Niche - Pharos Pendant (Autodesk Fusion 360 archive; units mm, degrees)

design "Pharos" references "Pharos", "Niche - Chief Architect - Luxe Single Pendant Cordset", "Luxe Single Pendant Cordset - 4ft Standard"
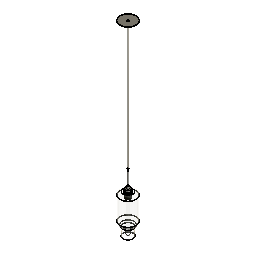
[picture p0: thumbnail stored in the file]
external_derived "ExternalDerived1"
external_derived "ExternalDerived2" bodies "Socket Body", "Shade Ring", "Shade Ring +Collar", "Socket", "Body1 (1)", "Metal Strain Relief", "Fabric Cord (1)", "Stem (Threaded)"
move "Move1"
external_derived "ExternalDerived3" bodies "T8-Bulb"
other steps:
derived_base_feature "Derived Base Feature1" bodies "Body1"
derived_base_feature "Derived Base Feature2" bodies "Socket Body", "Shade Ring", "Shade Ring +Collar", "Socket", "Body1 (1)", "Metal Strain Relief", "Fabric Cord (1)", "Stem (Threaded)"
derived_base_feature "Derived Base Feature3" bodies "T8-Bulb"
named bodies: "Body1", "Socket Body", "Shade Ring", "Shade Ring +Collar", "Socket", "Body1 (1)", "Metal Strain Relief", "Fabric Cord (1)", "Stem (Threaded)", "Cap (Threaded)", "T8-Bulb"

design "Luxe Single Pendant Cordset - 4ft Standard" references "Luxe Canopy - Single Pendant Cordset"
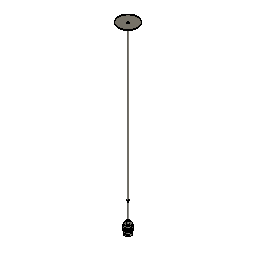
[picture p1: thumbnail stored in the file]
external_derived "ExternalDerived2" bodies "Cap (Threaded)"
move "Move1"
move "Move2"
offset_faces "OffsetFaces1" distance 1051.56
move "Move3"
move "Move4"
move "Move5"
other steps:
derived_base_feature "Derived Base Feature9" bodies "Socket Body", "Shade Ring", "Shade Ring +Collar", "Socket"
derived_base_feature "Derived Base Feature10" bodies "Body1"
derived_base_feature "Derived Base Feature12" bodies "Metal Strain Relief"
derived_base_feature "Derived Base Feature13" bodies "Fabric Cord (1)"
derived_base_feature "Derived Base Feature14" bodies "Stem (Threaded)"
derived_base_feature "Derived Base Feature15" bodies "Cap 9Threaded)", "Cap (Threaded)"
named bodies: "Socket Body", "Shade Ring", "Shade Ring +Collar", "Socket", "Metal Strain Relief", "Fabric Cord (1)", "Stem (Threaded)", "Cap 9Threaded)", "Body1", "Cap (Threaded)", "5M Set Screw"

design "Pharos"
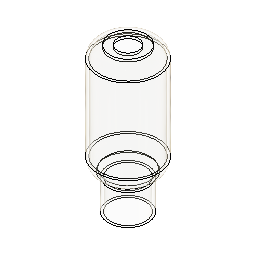
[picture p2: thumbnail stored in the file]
sketch "Sketch1" plane through (0, 0, 0) normal (0, 1, 0) x axis (1, 0, 0)
  line L1 (63.5, 0) -> (25.4, 0)
  line L2 (0, -234.95) -> (0, -25.4)
  line L3 (63.5, -368.3) -> (63.5, 0)
  line L4 (95.1552, -330.2058) -> (22.1208, -330.198)
  line L5 (88.9054, -330.2051) -> (95.1552, -330.2058)
  line L6 (127, -381) -> (0, -381)
  line L7 (63.5, -438.8463) -> (63.5, -381)
  line L8 (104.775, -409.9232) -> (63.5, -409.9232)
  line L9 (22.225, -409.9232) -> (63.5, -409.9232)
  line L10 (22.225, -342.9604) -> (22.225, -409.9232)
  line L11 (98.425, -234.95) -> (98.425, 0)
  line L12 (22.1304, -240.8815) -> (22.1208, -330.198)
  arc A1 centre (25.4, -25.4) radius 25.4 clockwise from (0, -25.4) to (25.4, 0)
  arc A2 centre (30.6129, -203.4011) radius 30.6143 clockwise from (15.9842, -230.2942) to (0, -203.1036)
  arc A3 centre (9.9384, -240.8815) radius 12.192 clockwise from (15.9842, -230.2942) to (22.1304, -240.8841)
  point P9 (88.9054, -330.2051)
  point P12 (63.5, -381)
  point P14 (63.5, -409.9232)
  point P21 (0, -203.1036)
  point P26 (22.1304, -240.8841)
  point P24 (22.1304, -240.8815)
  point P1 (0, 0)
  point P6 (0, -234.95)
  point P10 (0, -381)
  point P11 (127, -381)
  point P15 (104.775, -409.9232)
  point P16 (22.225, -409.9232)
  point P18 (98.425, 0)
  point P19 (98.425, -234.95)
  perpendicular L1 L3
  coincident L4 P9
  midpoint L6 P12
  perpendicular L6 L7
  midpoint L7 P14
  perpendicular L7 L8
  perpendicular L7 L9
  perpendicular L9 L10
  vertical L11
  coincident L2 P21
  perpendicular L4 L12
  coincident L12 P26
  coincident P24 A3
  dimension "d1" diameter A1 = 50.8
  dimension "d4" distance P1 P6 = 234.95
  dimension "d12" distance P10 P11 = 127
  dimension "d13" distance P14 P15 = 41.275
  dimension "d14" distance P14 P16 = 41.275
  dimension "d15" distance P18 P19 = 234.95
  dimension "d20" diameter A3 = 24.384
revolve "Revolve1" sketch "Sketch1" AlongAngle 360
offset_faces "OffsetFaces1" distance -25.4
shell "Shell1" innerThickness 5
sketch "Sketch2" plane through (0, 0, 0) normal (0, 0, -1) x axis (1, 0, 0)
  circle C1 centre (63.5, 0) radius 38.1
  circle C2 centre (63.5, 0) radius 22.225
  concentric C1 C2
  dimension "d23" diameter C2 = 44.45 (= "1 3/4")
extrude "Extrude1" cut sketch "Sketch2" profile of C2 against normal blind 50.8
move "Move1"

design "Luxe Canopy - Single Pendant Cordset" references "M5 Set Screw", "Canopy Mounting Bar", "Plastic Strain Relief", "Canopy Mounting Bar Screw", "Luxe Cordset"
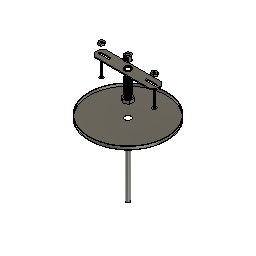
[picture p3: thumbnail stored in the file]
sketch "Sketch1" plane through (0, 0, 0) normal (0, 0, 1) x axis (1, 0, 0)
  circle C1 centre (0, 0) radius 63.5
  point P1 (0, 0)
  point P2 (0, 0)
  coincident P1 P2
  dimension "d1" diameter C1 = 127
extrude "Extrude1" new body sketch "Sketch1" along normal blind 5.08
shell "Shell1" innerThickness 0.762
hole "Hole1" HoleDepth 35.56 HoleDiameter 10.16 TipAngle 118
component_from_bodies "Body->Comp1"
component_insert "Component Insert1"
component_insert "Component Insert2"
component_insert "Component Insert3"
sketch "Sketch2" plane through (0, 0, 0) normal (0, 0, 1) x axis (1, 0, 0)
  circle C1 centre (0, 0) radius 3.175
  point P1 (0, 0)
  point P2 (0, 0)
  coincident P1 P2
  dimension "d8" diameter C1 = 6.35
extrude "Extrude2" new body sketch "Sketch2" along normal blind 127 and against normal blind 127 bodies "Fabric Cord"
component_insert "Component Insert4"
component_insert "Component Insert5"
position "Position1"
sketch "Sketch3" plane through (0, 0, 0.762) normal (0, 0, 1) x axis (-1, 0, 0)
  circle C1 centre (-0.0475, 0.2257) radius 5.08
  circle C2 centre (0, 0) radius 62.738
  circle C3 centre (0, 0) radius 4.826
  concentric C2 C3
  dimension "d13" diameter C3 = 9.652
extrude "Extrude3" new body sketch "Sketch3" profile of C3 along normal blind 25.4 bodies "Threaded Nipple"
shell "Shell2" innerThickness 1.27
thread "Thread1"
sketch "Sketch5" plane through (0, 0, 127) normal (0, 0, 1) x axis (-1, 0, 0)
  line L1 (-6.8191, 3.937) -> (0, 7.874)
  line L2 (-6.8191, -3.937) -> (-6.8191, 3.937)
  line L3 (0, -7.874) -> (-6.8191, -3.937)
  line L4 (6.8191, -3.937) -> (0, -7.874)
  line L5 (6.8191, 3.937) -> (6.8191, -3.937)
  line L6 (0, 7.874) -> (6.8191, 3.937)
  circle C1 centre (0, 0) radius 3.175
  point P2 (0, 0)
  point P9 (0, 0)
  point P3 (0, 7.874)
  coincident P2 P9
  dimension "d20" distance P3 P9 = 7.874
extrude "Extrude4" new body sketch "Sketch5" along normal blind 5.08 bodies "Hex Nut"
move "Move1"
thread "Thread2"
move "Move2" TranslateX 0 TranslateY 0 TranslateZ -55.88
move "Move3" TranslateX 0 TranslateY 0 TranslateZ 60.96
position "Position2"
sketch "Sketch6" plane through (0, 0, 0) normal (0, 0, 1) x axis (1, 0, 0)
  circle C1 centre (0, 0) radius 9.525
  point P1 (0, 0)
  point P2 (0, 0)
  coincident P1 P2
  dimension "d29" diameter C1 = 19.05
extrude "Extrude5" new body sketch "Sketch6" along normal blind 16.129 bodies "Metal Strain Relief"
move "Move4" TranslateX 0 TranslateY 0 TranslateZ -86.36
hole "Hole2" HoleDepth 10.16 HoleDiameter 5.08 TipAngle 118
hole "Hole3" HoleDepth 4.064 HoleDiameter 7.62 TipAngle 180
hole "Hole4" HoleDepth 12.192 HoleDiameter 9.144 TipAngle 180
thread "Thread3" ThreadOffset 0 ThreadLength 6.096
move "Move1" TranslateX 0 TranslateY 0 TranslateZ 68.58
move "Move5" TranslateX 0 TranslateY 0 TranslateZ 138.43
component_insert "Component Insert6"
external_derived "ExternalDerived1" bodies "5M Set Screw"
move "Move6" TranslateX 0 TranslateY 0 TranslateZ -185.42
copy_paste_bodies "CopyPasteBodies1"
move "Move7" TranslateX 0 TranslateY 0 TranslateZ -12.7
offset_faces "OffsetFaces1" distance -152.4
move "Move8"
component_from_bodies "Body->Comp2"
component_from_bodies "Body->Comp3"
component_from_bodies "Body->Comp4"
component_from_bodies "Body->Comp5"
hole "Hole1" HoleDepth 25.4 HoleDiameter 6.35 TipAngle 180
sketch "Sketch7" plane through (0, 0, 0) normal (0, 0, 1) x axis (1, 0, 0)
  line L1 (49.784, 3.9595) -> (52.07, 0)
  line L2 (45.212, 3.9595) -> (49.784, 3.9595)
  line L3 (42.926, 0) -> (45.212, 3.9595)
  line L4 (45.212, -3.9595) -> (42.926, 0)
  line L5 (49.784, -3.9595) -> (45.212, -3.9595)
  line L6 (52.07, 0) -> (49.784, -3.9595)
  point P2 (52.07, 0)
  point P8 (47.498, 0)
  dimension "d63" distance P2 P8 = 4.572
extrude "Extrude6" new body sketch "Sketch7" along normal blind 3.175 bodies "Mounting Hex Nut"
hole "Hole5" HoleDepth 25.4 HoleDiameter 3.81 TipAngle 180
thread "Thread4"
move "Move9"
component_from_bodies "Body->Comp6"
copy_paste "CopyPaste1"
move "Move10"
derived_base_feature "Derived Base Feature3" bodies "Stem (Threaded)", "Cap 9Threaded)"
move "Move11"
component_from_bodies "Body->Comp7"
component_from_bodies "Body->Comp8"
component_from_bodies "Body->Comp9"
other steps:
base_feature "Base Feature1"
base_feature "Base Feature1" bodies "Stem (Threaded)"
base_feature "Base Feature1" bodies "Cap 9Threaded)"
base_feature "Base Feature1" bodies "Fabric Cord"
base_feature "Base Feature1" bodies "Metal Strain Relief"
base_feature "Base Feature1" bodies "Mounting Hex Nut"
base_feature "Base Feature1" bodies "Hex Nut"
base_feature "Base Feature1" bodies "Fabric Cord (1)"
base_feature "Base Feature1" bodies "Threaded Nipple"
derived_base_feature "Derived Base Feature1" bodies "Socket Body", "Shade Ring", "Shade Ring +Collar", "Socket", "Rigid Stem"
derived_base_feature "Derived Base Feature2" bodies "5M Set Screw"
base_feature "Base Feature1" bodies "Fabric Cord", "Fabric Cord (1)"
create_component "CreateComponent1"
remove_body "RemoveBody1"
create_component "CreateComponent2"
remove_body "RemoveBody2"
create_component "CreateComponent3"
remove_body "RemoveBody3"
create_component "CreateComponent4"
remove_body "RemoveBody4"
create_component "CreateComponent5"
remove_body "RemoveBody5"
create_component "CreateComponent6"
remove_body "RemoveBody6"
create_component "CreateComponent7"
remove_body "RemoveBody7"
create_component "CreateComponent8"
remove_body "RemoveBody8"
create_component "CreateComponent9"
remove_body "RemoveBody9"
named bodies: "Fabric Cord", "Threaded Nipple", "Hex Nut", "Metal Strain Relief", "Socket Body", "Shade Ring", "Shade Ring +Collar", "Socket", "Rigid Stem", "5M Set Screw", "Fabric Cord (1)", "Mounting Hex Nut", "Stem (Threaded)", "Cap 9Threaded)"

design "M5 Set Screw"
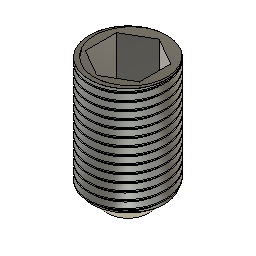
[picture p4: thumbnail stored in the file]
sketch "Sketch1" plane through (0, 0, 0) normal (0, 0, 1) x axis (1, 0, 0)
  circle C1 centre (0, 0) radius 2.5
  point P1 (0, 0)
  point P2 (0, 0)
  coincident P1 P2
  dimension "d1" diameter C1 = 5
extrude "Extrude1" new body sketch "Sketch1" along normal blind 8
sketch "Sketch2" plane through (0, 0, 8) normal (0, 0, 1) x axis (-1, 0, 0)
  line L1 (-1.7321, 1) -> (0, 2)
  line L2 (-1.7321, -1) -> (-1.7321, 1)
  line L3 (0, -2) -> (-1.7321, -1)
  line L4 (1.7321, -1) -> (0, -2)
  line L5 (1.7321, 1) -> (1.7321, -1)
  line L6 (0, 2) -> (1.7321, 1)
  circle C1 centre (0, 0) radius 2.5
  point P2 (0, 0)
  point P9 (0, 0)
  coincident P2 P9
extrude "Extrude2" cut sketch "Sketch2" profile of L1 L2 L3 L4 L5 L6 against normal blind 3
thread "Thread1" ThreadOffset 0.99 ThreadLength 7
chamfer "Chamfer1" distance 1.15

design "Luxe Cordset" references "M5 Set Screw"
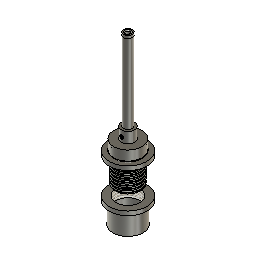
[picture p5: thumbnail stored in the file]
sketch "Sketch1" plane through (0, 0, 0) normal (0, 0, 1) x axis (1, 0, 0)
  circle C1 centre (0, 0) radius 20.6
  point P1 (0, 0)
  point P2 (0, 0)
  coincident P1 P2
  dimension "d11" diameter C1 = 41.2
extrude "Extrude1" new body sketch "Sketch1" along normal blind 14 bodies "Socket Body"
sketch "Sketch2" plane through (0, 0, 14) normal (0, 0, 1) x axis (-1, 0, 0)
  circle C1 centre (0, 0) radius 20.6
  circle C2 centre (0, 0) radius 9.6
  concentric C1 C2
  dimension "d3" diameter C2 = 19.2
extrude "Extrude2" add sketch "Sketch2" profile of C2 along normal blind 15.75
sketch "Sketch3" plane through (0, 0, 29.75) normal (0, 0, 1) x axis (-1, 0, 0)
  circle C1 centre (0, 0) radius 9.6
  circle C2 centre (0, 0) radius 5.75
  concentric C1 C2
  dimension "d6" diameter C2 = 11.5
extrude "Extrude3" new body sketch "Sketch3" profile of C2 along normal blind 114 bodies "Rigid Stem"
move "Move1"
sketch "Sketch4" plane through (0, 0, 203.75) normal (0, 0, 1) x axis (-1, 0, 0)
  circle C1 centre (0, 0) radius 5.75
  circle C2 centre (0, 0) radius 27.5
  dimension "d10" diameter C2 = 55
extrude "Extrude4" new body sketch "Sketch4" profile of C2 along normal blind 6 bodies "Shade Ring"
hole "Hole1" HoleDepth 25 HoleDiameter 42.75 TipAngle 118
sketch "Sketch5" plane through (0, 0, 0) normal (0, 0, 1) x axis (1, 0, 0)
  circle C1 centre (0, 0) radius 22
  point P1 (0, 0)
  point P2 (0, 0)
  coincident P1 P2
  dimension "d18" diameter C1 = 44
move "Move2"
copy_paste_bodies "CopyPasteBodies1"
move "Move3"
sketch "Sketch6" plane through (0, 0, 60) normal (0, 0, -1) x axis (1, 0, 0)
  circle C1 centre (0, 0) radius 20.6
  circle C2 centre (0, 0) radius 21.375
  circle C3 centre (0, 0) radius 20
  concentric C1 C2
  concentric C1 C3
  dimension "d21" diameter C2 = 42.75
  dimension "d24" diameter C3 = 40
cylinder_primitive "CylinderPrimitive1" Height 8 Diameter 42.75
thread "Thread1"
thread "Thread3"
hole "Hole2" HoleDepth 18 HoleDiameter 39 TipAngle 180
move "Move4"
move "Move5"
move "Move6"
hole "Hole3" HoleDepth 114 HoleDiameter 7.6 TipAngle 180
derived_base_feature "Derived Base Feature" bodies "Socket"
move "Move7"
scale "Scale1" ScaleX 1.2 ScaleY 1.2
move "Move8"
sketch "Sketch8" plane through (0, 0, -23.9827) normal (0, 0, -1) x axis (1, 0, 0)
  circle C1 centre (0, -0.036) radius 27.5
  circle C2 centre (0, -0.036) radius 22
  circle C3 centre (0, -0.036) radius 19.5
  dimension "d36" diameter C2 = 44
  dimension "d42" = -2.5
extrude "Extrude7" add sketch "Sketch8" profile of C2 C3 along normal blind 30
offset_faces "OffsetFaces1" distance 2.75
offset_faces "OffsetFaces2" distance -9
thread "Thread2"
move "Move9"
move "Move10"
move "Move11"
scale "Scale2" ScaleZ 1.2
move "Move12"
move "Move13"
move "Move14"
move "Move15"
move "Move16"
split_face "SplitFace1"
move "Move17"
move "Move18"
move "Move19"
move "Move20"
move "Move21"
move "Move22"
move "Move23"
move "Move24"
move "Move25"
move "Move26"
move "Move27"
thread "Thread4"
move "Move28"
move "Move29"
move "Move30"
hole "Hole4" HoleDepth 21 HoleDiameter 39.35 TipAngle 180
hole "Hole5" HoleDepth 9 HoleDiameter 5 TipAngle 180
move "Move31"
move "Move32"
hole "Hole6" HoleDepth 20 HoleDiameter 10 TipAngle 180
move_face "MoveFace3"
move "Move33"
move "Move34"
move "Move35"
move "Move36"
move "Move37"
thread "Thread5" ThreadOffset 0 ThreadLength 6
thread "Thread6" ThreadOffset 0 ThreadLength 6
move "Move38"
move "Move39"
move "Move40"
move "Move41"
component_insert "Component Insert"
thread "Thread7" ThreadOffset 0.5 ThreadLength 5.337
chamfer "Chamfer1" distance 0.5 distance 0.35
sketch "Sketch12" plane through (0, 0, 0) normal (0, 0, 1) x axis (1, 0, 0)
  circle C1 centre (0, 0) radius 6.35
  dimension "d60" diameter C1 = 12.7
extrude "Extrude8" new body sketch "Sketch12" along normal blind 115 bodies "Stem (Threaded)"
hole "Hole7" HoleDepth 115 HoleDiameter 9.65 TipAngle 118
thread "Thread8" ThreadOffset 0 ThreadLength 12.5
thread "Thread9" ThreadOffset 0 ThreadLength 12.5
sketch "Sketch13" plane through (0, 0, 0) normal (0, 0, 1) x axis (1, 0, 0)
  circle C1 centre (0, 0) radius 6.35
  point P1 (0, 0)
  point P2 (0, 0)
  coincident P1 P2
  dimension "d70" diameter C1 = 12.7
extrude "Extrude9" new body sketch "Sketch13" along normal blind 4 bodies "Cap 9Threaded)"
sketch "Sketch14" plane through (0, 0, 4) normal (0, 0, 1) x axis (-1, 0, 0)
  circle C1 centre (0, 0) radius 6.35
  circle C2 centre (0, 0) radius 4.5
  concentric C1 C2
  dimension "d73" diameter C2 = 9
extrude "Extrude10" add sketch "Sketch14" profile of C2 against normal blind 14
thread "Thread10"
hole "Hole8" HoleDepth 115 HoleDiameter 6.5 TipAngle 118 CSDiameter 9 CSAngle 90
move "Move42"
move "Move43"
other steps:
base_feature "Base Feature" bodies "Shade Ring +Collar"
named bodies: "Socket Body", "Shade Ring", "Shade Ring +Collar", "Socket", "Rigid Stem", "Stem (Threaded)", "Cap 9Threaded)"

design "Plastic Strain Relief"
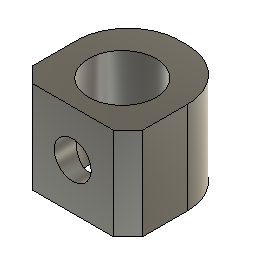
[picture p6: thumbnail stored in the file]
base_feature "Base Feature" bodies "strainrelief"
named bodies: "strainrelief"

design "Canopy Mounting Bar Screw"
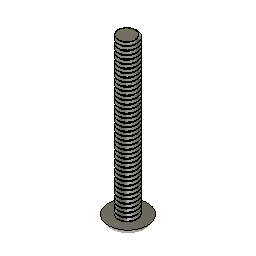
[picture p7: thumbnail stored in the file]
base_feature "Base Feature" bodies "screw1"
named bodies: "screw1"

design "Canopy Mounting Bar"
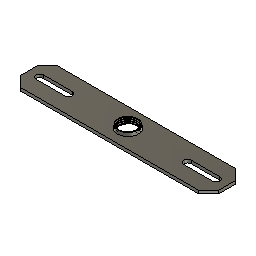
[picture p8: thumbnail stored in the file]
base_feature "Base Feature" bodies "mountingbar"
named bodies: "mountingbar"

design "Niche - Chief Architect - Luxe Single Pendant Cordset"
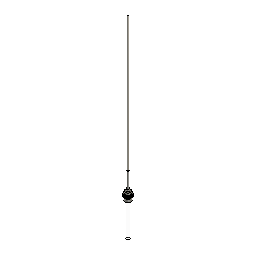
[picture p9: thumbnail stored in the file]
derived_base_feature "Derived Base Feature" bodies "Socket Body", "Shade Ring", "Shade Ring +Collar", "Socket", "Canopy", "Metal Strain Relief", "Fabric Cord (1)", "Stem (Threaded)"
remove_body "RemoveBody1"
remove_body "RemoveBody2"
split "Split1" bodies "Socket Body (1)"
remove_body "RemoveBody3"
align "Align1"
hole "Hole1" HoleDepth 19.05 HoleDiameter 8.89 TipAngle 118
combine "Combine1" bodies "Shade Ring"
split "Split2" bodies "Socket (1)"
remove_body "RemoveBody4"
split "Split3" bodies "Fabric Cord (1) (1)"
remove_body "RemoveBody5"
combine "Combine2" bodies "Socket Body"
align "Align2"
combine "Combine3" bodies "Metal Strain Relief"
sketch "Sketch1" plane through (0, 0, 0) normal (0, 1, 0) x axis (1, 0, 0)
  line L1 (13.1098, 24.9049) -> (-12.2902, 24.9049)
  line L2 (18.1898, 37.1766) -> (18.1898, 29.9849)
  line L3 (-17.3702, 29.9849) -> (-17.3702, 36.7132)
  line L4 (0, 132.969) -> (0, 24.9049)
  arc A1 centre (0, 86.36) radius 46.609 clockwise from (-22.6031, 45.5985) to (23.276, 45.979)
  arc A2 centre (-27.5302, 36.7132) radius 10.16 clockwise from (-22.6031, 45.5985) to (-17.3702, 36.7132)
  arc A3 centre (28.3498, 37.1766) radius 10.16 clockwise from (18.1898, 37.1766) to (23.276, 45.979)
  arc A4 centre (-12.2902, 29.9849) radius 5.08 clockwise from (-12.2902, 24.9049) to (-17.3702, 29.9849)
  arc A5 centre (13.1098, 29.9849) radius 5.08 clockwise from (18.1898, 29.9849) to (13.1098, 24.9049)
  point P5 (18.1898, 43.4469)
  point P3 (-17.3702, 24.9049)
  point P4 (18.1898, 24.9049)
  point P18 (0, 24.9049)
  point P19 (0, 132.969)
  horizontal L1
  vertical L2
  vertical L3
  tangent A1 A2
  tangent L3 A2
  coincident P5 L2
  coincident P5 A1
  tangent L2 A3
  tangent A1 A3
  equal A2 A3
  coincident P3 L1
  coincident P3 L3
  tangent L1 A4
  tangent L3 A4
  coincident P4 L1
  coincident P4 L2
  tangent L1 A5
  tangent L2 A5
  coincident L1 P18
  coincident A1 P19
  perpendicular L1 L4
  dimension "d4" diameter A1 = 93.218
  dimension "d5" distance P3 P4 = 35.56
  dimension "d6" distance P4 P5 = 18.542
  dimension "d7" radius A2 = 10.16
  dimension "d8" radius A4 = 5.08
  dimension "d9" radius A5 = 5.08
revolve "Revolve1" sketch "Sketch1" AlongAngle 360 bodies "G30-Bulb"
move "Move1"
sketch "Sketch2" plane through (0, 0, 0) normal (0, 1, 0) x axis (1, 0, 0)
  line L1 (12.7, 0) -> (-12.7, 0)
  line L2 (12.7, 152.4) -> (12.7, 0)
  line L3 (-12.7, 0) -> (-12.7, 152.4)
  line L4 (0, 165.1) -> (0, 0)
  arc A1 centre (0, 152.4) radius 12.7 clockwise from (-12.7, 152.4) to (12.7, 152.4)
  point P1 (0, 0)
  point P7 (0, 0)
  point P8 (0, 165.1)
  horizontal L1
  vertical L2
  vertical L3
  coincident P1 P7
  midpoint A1 P8
  perpendicular L1 L4
revolve "Revolve2" sketch "Sketch2" AlongAngle 360 bodies "T9-Bulb"
move "Move2"
sketch "Sketch3" plane through (0, 0, 0) normal (0, 1, 0) x axis (1, 0, 0)
  line L1 (12.7, 0) -> (-12.7, 0)
  line L2 (12.7, 254) -> (12.7, 0)
  line L3 (-12.7, 0) -> (-12.7, 254)
  line L4 (0, 266.7) -> (0, 0)
  arc A1 centre (0, 254) radius 12.7 clockwise from (-12.7, 254) to (12.7, 254)
  point P1 (0, 0)
  point P7 (0, 0)
  point P8 (0, 266.7)
  horizontal L1
  vertical L2
  vertical L3
  coincident P1 P7
  midpoint A1 P8
  perpendicular L1 L4
revolve "Revolve3" sketch "Sketch3" AlongAngle 360 bodies "T8-Bulb"
move "Move3"
move "Move4"
move "Move5"
sketch "Sketch4" plane through (0, 0, 0) normal (0, 1, 0) x axis (1, 0, 0)
  line L1 (15.875, -8.763) -> (-15.875, -8.763)
  line L2 (15.875, 22.987) -> (15.875, -8.763)
  line L3 (-15.875, 22.987) -> (15.875, 22.987)
  line L4 (-15.875, -8.763) -> (-15.875, 22.987)
  line L5 (0, 22.987) -> (0, -8.763)
  point P6 (0, -8.763)
  point P7 (0, 22.987)
  point P2 (-15.875, -8.763)
  point P3 (15.875, -8.763)
  point P5 (-15.875, 22.987)
  horizontal L1
  vertical L2
  horizontal L3
  vertical L4
  midpoint L1 P6
  midpoint L3 P7
  dimension "d13" distance P2 P3 = 31.75
  dimension "d14" distance P2 P5 = 31.75
revolve "Revolve4" sketch "Sketch4" AlongAngle 360 bodies "Bulb Extender"
move "Move6"
sketch "Sketch5" plane through (0, 0, 0) normal (0, 1, 0) x axis (1, 0, 0)
  line L1 (-12.7, 35.56) -> (12.7, 35.56)
  line L2 (-12.7, 5.08) -> (-12.7, 35.56)
  line L3 (12.7, 5.08) -> (-12.7, 5.08)
  line L4 (12.7, 35.56) -> (12.7, 5.08)
  line L5 (-12.7, 5.08) -> (12.7, 35.56)
  line L6 (12.7, 5.08) -> (-12.7, 35.56)
  line L7 (0, 35.56) -> (0, 5.08)
  point P6 (0, 20.32)
  point P7 (0, 5.08)
  point P8 (0, 35.56)
  horizontal L1
  perpendicular L1 L2
  parallel L1 L3
  parallel L2 L4
  coincident L5 P6
  coincident L6 P6
  midpoint L3 P7
  midpoint L1 P8
revolve "Revolve5" sketch "Sketch5" AlongAngle 360 bodies "Y-Spliter"
sketch "Sketch6" plane through (0, 0, 0) normal (0, 1, 0) x axis (1, 0, 0)
  line L1 (-55.88, 64.9514) -> (-21.59, 64.9514)
  line L2 (-55.88, 35.7414) -> (-55.88, 64.9514)
  line L3 (-21.59, 35.7414) -> (-55.88, 35.7414)
  line L4 (-21.59, 64.9514) -> (-21.59, 35.7414)
  line L5 (-55.88, 35.7414) -> (-21.59, 64.9514)
  line L6 (-21.59, 35.7414) -> (-55.88, 64.9514)
  line L7 (-38.735, 64.9514) -> (-38.735, 35.7414)
  point P6 (-38.735, 50.3464)
  point P7 (-38.735, 35.7414)
  point P8 (-38.735, 64.9514)
  point P4 (-55.88, 35.7414)
  point P5 (-21.59, 35.7414)
  point P2 (-21.59, 64.9514)
  horizontal L1
  perpendicular L1 L2
  parallel L1 L3
  parallel L2 L4
  coincident L5 P6
  coincident L6 P6
  midpoint L3 P7
  midpoint L1 P8
  dimension "d17" distance P4 P5 = 34.29
  dimension "d18" distance P2 P5 = 29.21
revolve "Revolve6" sketch "Sketch6" AlongAngle 360
chamfer "Chamfer1" distance 7.62
move "Move7"
mirror "Mirror1" mirrorStitchTolerance 0.1016
move "Move8"
combine "Combine4"
move "Move9"
sketch "Sketch7" plane through (0, 0, 0) normal (0, 1, 0) x axis (1, 0, 0)
  line L1 (-15.24, 40.64) -> (-15.24, 48.1816)
  line L2 (12.7, 38.1) -> (-12.7, 38.1)
  line L3 (15.24, 48.1816) -> (15.24, 40.64)
  line L4 (0, 100.1623) -> (0, 38.1)
  arc A1 centre (0, 76.2) radius 23.9623 clockwise from (-19.7282, 62.5988) to (19.7282, 62.5988)
  arc A2 centre (-40.64, 48.1816) radius 25.4 clockwise from (-19.7282, 62.5988) to (-15.24, 48.1816)
  arc A3 centre (40.64, 48.1816) radius 25.4 clockwise from (15.24, 48.1816) to (19.7282, 62.5988)
  arc A4 centre (-12.7, 40.64) radius 2.54 clockwise from (-12.7, 38.1) to (-15.24, 40.64)
  arc A5 centre (12.7, 40.64) radius 2.54 clockwise from (15.24, 40.64) to (12.7, 38.1)
  point P15 (0, 38.1)
  point P16 (0, 100.1623)
  parallel L1 L3
  tangent A1 A2
  tangent L1 A2
  tangent A1 A3
  tangent L3 A3
  tangent L1 A4
  tangent L2 A4
  tangent L2 A5
  tangent L3 A5
  midpoint L2 P15
  midpoint A1 P16
  perpendicular L2 L4
  dimension "d23" radius A2 = 25.4
  dimension "d24" radius A3 = 25.4
  dimension "d25" radius A4 = 2.54
  dimension "d26" radius A5 = 2.54
revolve "Revolve7" sketch "Sketch7" AlongAngle 360 bodies "A15-Bulb"
move "Move10"
copy_paste_bodies "CopyPasteBodies1"
copy_paste_bodies "CopyPasteBodies2"
move "Move11"
mirror "Mirror2" mirrorStitchTolerance 0.1016 bodies "A15-Bulb (1) (1)"
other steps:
base_feature "Base Feature1" bodies "Y-Spliter", "Bulb Extender", "Y-Spliter (1)", "Bulb Extender (1)"
base_feature "Base Feature2" bodies "A15-Bulb", "A15-Bulb (1)"
named bodies: "Socket Body", "Shade Ring", "Shade Ring +Collar", "Socket", "Canopy", "Metal Strain Relief", "Fabric Cord (1)", "Stem (Threaded)", "Adapter", "5M Set Screw", "Body1 (1)", "Socket Body (1)", "Socket (1)", "Fabric Cord (1) (1)", "G30-Bulb", "T9-Bulb", "T8-Bulb", "Bulb Extender", "Y-Spliter", "A15-Bulb", "Y-Spliter (1)", "Bulb Extender (1)", "A15-Bulb (1)", "A15-Bulb (1) (1)"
